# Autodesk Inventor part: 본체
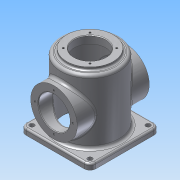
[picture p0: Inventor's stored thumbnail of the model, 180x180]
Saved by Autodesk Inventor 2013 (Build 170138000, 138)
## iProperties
Created: 2015-10
Part Number: 본체
Material: 알루미늄 6061
Document SubType Name: Modeling
Designer: Administrator
Density: 2.71 g/cm^3
Mass: 985.996 g
Surface Area: 1037.34 cm^2
Volume: 363.836 cm^3
Author: Administrator
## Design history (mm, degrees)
sketch "스케치1"
  geometry: C1 r 50 at (0, 0); 1 further point
  constraints: 1 centre point, 1 coincident
  dimensions: "d0" = 100 diameter of C1
extrude "돌출1" new body sketch "스케치1" stored distance "d2" = 110; taper "d3" = 0 deg
sketch "스케치2"
  geometry: L1 (-50, 60)-(50, 60); L2 (60, 50)-(60, -50); L3 (50, -60)-(-50, -60); L4 (-60, -50)-(-60, 50); A1 r 10 centre (-50, 50) between (-50, 60) and (-60, 50); A2 r 10 centre (-50, -50) between (-60, -50) and (-50, -60); A3 r 10 centre (50, -50) between (50, -60) and (60, -50); A4 r 10 centre (50, 50) between (60, 50) and (50, 60); 6 further points
  constraints: 8 end point, 8 point on circle, 8 tangent, 6 point on line, 4 centre point, 3 equal radius, 2 midpoint, 2 parallel, 1 horizontal, 1 horizontal alignment, 1 perpendicular, 1 vertical alignment
  dimensions: "d4" = 120 distance of point (60, 60) point (60, -60); "d6" = 120 distance of point (-60, 60) point (60, 60); "d7" = 10 radius of A1
extrude "돌출2" join sketch "스케치2" distance "d8" = 10; taper "d9" = 0 deg
sketch "스케치3"
  geometry: C1 r 40 at (0, 0); 1 further point
  constraints: 1 centre point, 1 coincident
  dimensions: "d10" = 80 diameter of C1
extrude "돌출3" join sketch "스케치3" distance "d12" = 5; taper "d13" = 0 deg
sketch "스케치5"
  geometry: L1 (-3.318, -19.887)-(-3.318, 29.887); L2 (-3.318, 29.887)-(3.886, 29.887); L3 (3.886, 29.887)-(3.886, -19.887); L4 (3.886, -19.887)-(-3.318, -19.887); L5 (-50, -65)-(50, -65) reference; 4 further points
  constraints: 2 midpoint, 1 horizontal alignment, 1 parallel, 1 vertical alignment, 2 other
  dimensions: "d18" = 70 distance from line of L5 point (0.284, 5); "d19" = 94.88738 distance between parallel lines of L2 L5; "d20" = 7.20489 distance between parallel lines of L3 L1; "d21" = 46.11352 distance from line of L5.end L3
feature "엠보싱1" sketch "스케치5" dims "d22" = 0.5, "d23" = 0
sketch "스케치9"
  geometry: L1 (-50, -65)-(50, -65) reference; C1 r 40 at (0, -5); 1 further point
  constraints: 1 centre point, 1 vertical alignment
  dimensions: "d51" = 60 distance from line of L1 C1.centre; "d52" = 80 diameter of C1
extrude "돌출5" join sketch "스케치9" stored distance "d53" = 124; taper "d54" = 0 deg
sketch "스케치6"
  geometry: L1 (-60, -50)-(-60, 50) reference; L2 (-50, 60)-(50, 60) reference; L3 (60, 50)-(60, -50) reference; L4 (50, -60)-(-50, -60) reference; 5 further points
  constraints: 2 horizontal alignment, 2 vertical alignment
  dimensions: "d24" = 10 distance from line of point (-50, 50) L2; "d25" = 10 distance from line of L1 point (-50, 50); "d26" = 10 distance from line of L4 point (50, -50); "d27" = 10 distance from line of L3 point (50, -50)
hole "구멍1" sketch "스케치6" at (-50, 50), (50, 50), (50, -50), (-50, -50) diameter "d28" = 8; stored, may be unused: countersink angle "d32" = 90 deg, drill point angle "d34" = 118 deg; dims "d29" = 6, "d30" = 4, "d31" = 2, "d33" = 8
sketch "스케치7"
  geometry: 2 further points
  constraints: 1 coincident
hole "구멍2" sketch "스케치7" at (0, 0) diameter "d35" = 54; stored, may be unused: countersink angle "d39" = 90 deg, drill point angle "d41" = 118 deg; dims "d36" = 6, "d37" = 90, "d38" = 112, "d40" = 8
hole "구멍4" diameter "d57" = 54; stored, may be unused: countersink angle "d61" = 90 deg, drill point angle "d63" = 118 deg; dims "d55" = 10, "d56" = 10, "d58" = 6, "d59" = 90, "d60" = 112, "d62" = 8
sketch "스케치10"
  geometry: L1 (-50, 60)-(50, 60) reference; 2 further points
  dimensions: "d64" = 32.5 horizontal distance of point (0, -5) point (-32.5, 0); "d65" = 60 distance from line of L1 point (-32.5, 0)
hole "구멍5" sketch "스케치10" at (-32.5, 0) diameter "d66" = 3.242; stored, may be unused: countersink angle "d70" = 90 deg, drill point angle "d72" = 118 deg; dims "d67" = 8, "d68" = 90, "d69" = 112, "d71" = 10
sketch "스케치11" dims "d77" = 65
  geometry: L1 (-50, 0)-(50, 0); L2 (0, 0)-(35.355, 35.355); L3 (0, 0)-(35.355, -35.355); A1 r 50 centre (0, 0) between (-50, 0) and (50, 0) reference; 4 further points
  constraints: 6 end point, 4 point on circle, 2 coincident, 1 horizontal, 1 midpoint, 1 perpendicular, 1 point on line, 3 other
  dimensions: "d76" = 45 deg angle of L1 L2
hole "구멍6" sketch "스케치11" at (22.981, 22.981) diameter "d79" = 3.242; stored, may be unused: countersink angle "d83" = 90 deg, drill point angle "d85" = 118 deg; dims "d80" = 8, "d81" = 4, "d82" = 2, "d84" = 10
chamfer "모따기1" distance "d89" = 1; stored, may be unused: second distance "d90" = 2, angle "d91" = 45 deg
chamfer "모따기2" distance "d92" = 3; stored, may be unused: second distance "d93" = 2, angle "d94" = 45 deg
chamfer "모따기3" distance "d95" = 1; stored, may be unused: second distance "d96" = 2, angle "d97" = 45 deg
fillet "모깎기1" dims "d98" = 5
fillet "모깎기2" dims "d99" = 5
fillet "모깎기3" dims "d100" = 5
fillet "모깎기4" dims "d101" = 3
fillet "모깎기5" dims "d102" = 3
fillet "모깎기6" dims "d103" = 3
fillet "모깎기7" dims "d104" = 3
node "솔리드1"
pattern_circular "원형 패턴1" dims angle "d74" = 360 deg
pattern_circular "원형 패턴2" dims angle "d87" = 360 deg
mirror "대칭1"
